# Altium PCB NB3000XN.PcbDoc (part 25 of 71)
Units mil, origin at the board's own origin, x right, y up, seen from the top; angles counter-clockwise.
Board outline 9527.56 x 6929.77 mil, 6 copper layers (Top Layer, GND+SHIELD, MidLayer1, MidLayer2, P2 - 3V3+5V0, Bottom Layer), stack 62.375 mil thick; 832 components, 1027 nets, 4655 pads, 4981 vias.
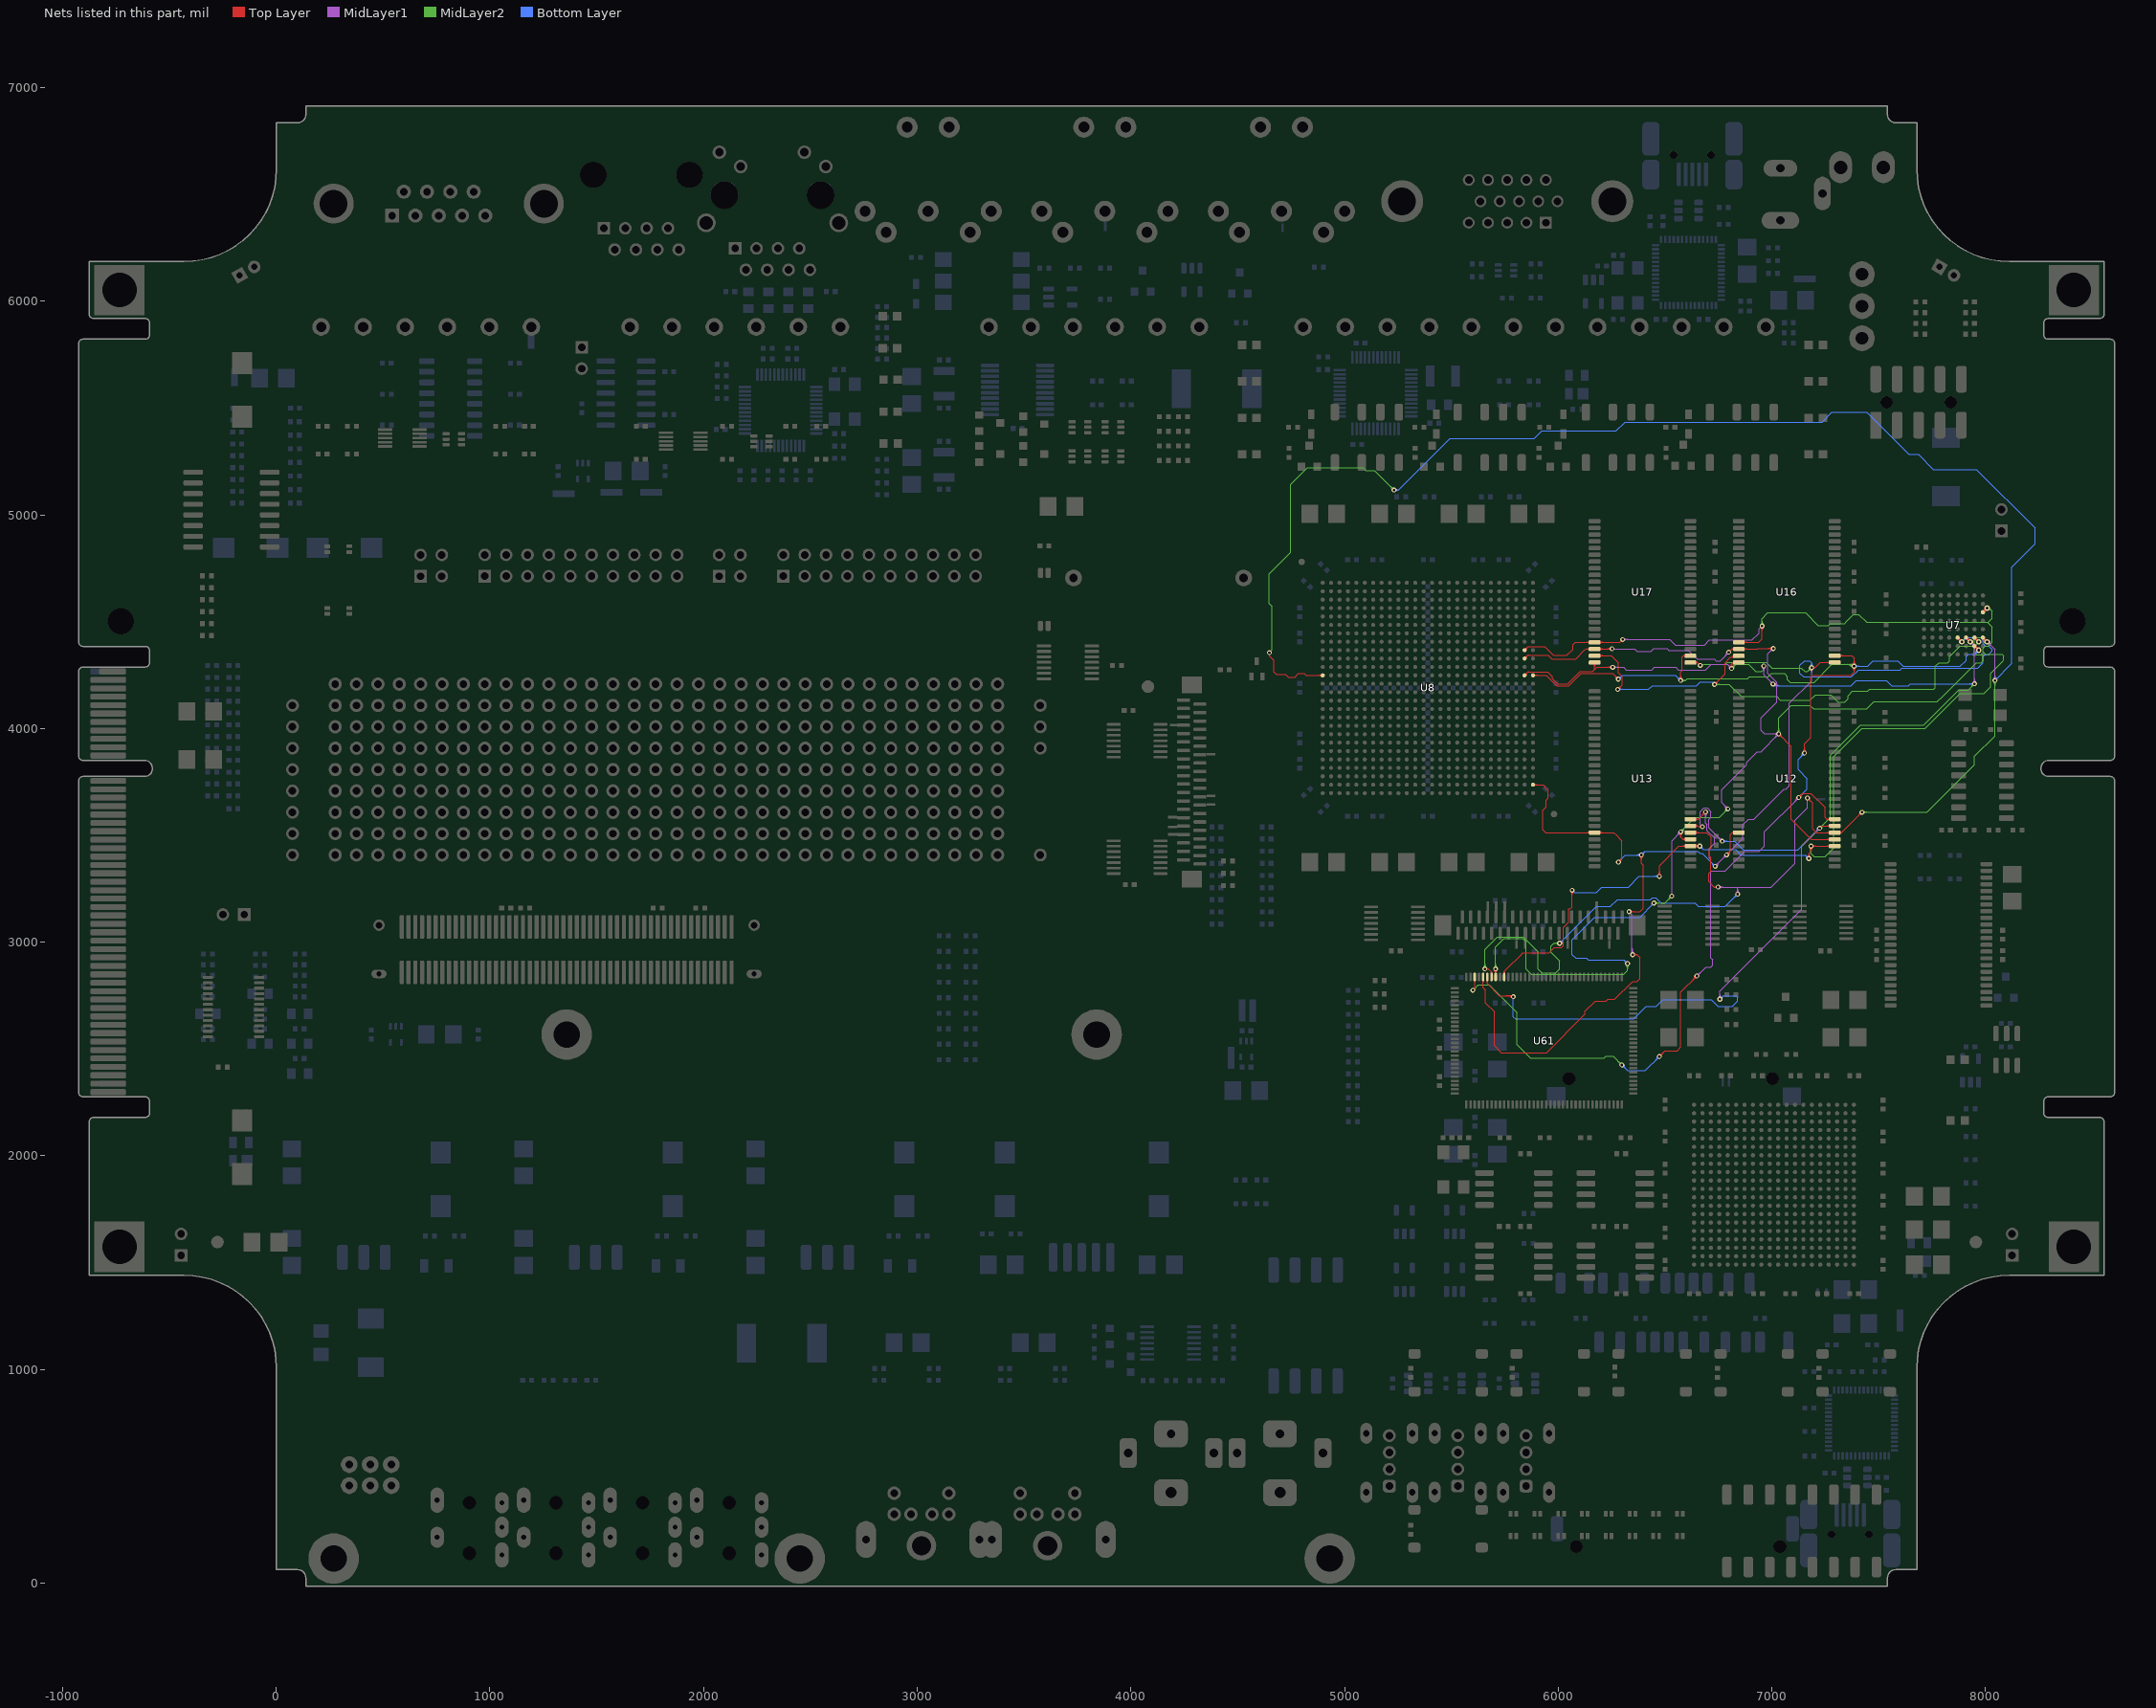
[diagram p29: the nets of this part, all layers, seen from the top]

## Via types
v1: diameter 23, hole 11.81, Top Layer to Bottom Layer, 3672 vias
v2: diameter 26, hole 11.81, Top Layer to Bottom Layer, 461 vias
v3: diameter 19, hole 11.81, Top Layer to Bottom Layer, tented both sides, 396 vias
v4: diameter 23.62, hole 11.81, Top Layer to Bottom Layer, 288 vias
v5: diameter 20, hole 11.81, Top Layer to Bottom Layer, 91 vias
v6: diameter 23, hole 11.81, Top Layer to Bottom Layer, tented both sides, 50 vias
v7: diameter 31, hole 11.81, Top Layer to Bottom Layer, 15 vias
v8: diameter 27.56, hole 11.81, Top Layer to Bottom Layer, tented both sides, 4 vias
v9: diameter 29, hole 11.81, Top Layer to Bottom Layer, 3 vias
v10: diameter 21, hole 11.81, Top Layer to Bottom Layer, 1 vias

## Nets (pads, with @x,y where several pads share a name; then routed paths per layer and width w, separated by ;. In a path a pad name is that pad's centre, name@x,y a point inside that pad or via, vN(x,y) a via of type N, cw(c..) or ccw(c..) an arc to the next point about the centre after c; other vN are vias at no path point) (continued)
DB_MEM.BUS_A8: U7.A3 U8.J25 U12.31 U13.31 U16.19 U17.19 U61.93 | length 7716.6
  Top Layer w4: U61.93@5744.34,2853.36 ccw(c5737.51,2860.19) 5747.17,2860.19 ccw(c5756.82,2860.19) U61.93@5749.99,2853.36 ; U61.93@5747.17,2837.34 5747.17,2862.68 5760.37,2875.89 5824.48,2940 5834.48,2950 5956.82,2950 5981.86,2975.04 6015.86,2975.04 6024.19,2983.37 6024.19,3070.04 6048.52,3094.37 6048.52,3154.04 6050.19,3155.71 6056.86,3155.71 6065.19,3164.04 v1(6065.19,3243.37) ; U8.J25@5842.76,4374.51 ccw(c5842.76,4392.23) 5855.29,4379.7 ; U8.J25@5850.1,4367.17 cw(c5867.83,4367.17) 5855.29,4379.7 ; v1@6058.47,3236.66 cw(c6042.26,3220.44) 6065.19,3220.44 cw(c6088.13,3220.44) v1@6071.91,3236.66 ; v1@6061.3,3239.49 cw(c6051.91,3230.1) 6065.19,3230.1 cw(c6078.47,3230.1) v1@6069.08,3239.49 ; U17.19@6147.37,4398.12 ccw(c6133.72,4384.47) 6133.72,4403.78 ccw(c6133.72,4423.09) U17.19@6147.37,4409.44 ; U17.19@6193.81,4398.12 cw(c6207.46,4384.47) 6207.46,4403.78 cw(c6207.46,4423.09) U17.19@6193.81,4409.44 ; v1(6301.86,4416.71) 6288.93,4403.78 U17.19@6170.59,4403.78 6080.86,4403.78 6068.86,4391.78 6068.86,4370.37 6041.19,4342.71 5976.52,4342.71 5936.56,4382.67 5924.74,4382.67 5920,4382.67 5910,4382.67 5862.47,4382.67 ccw(c5862.47,4372.52) 5855.29,4379.7 ; v1@6466.81,3315.09 ccw(c6450.59,3331.31) 6473.52,3331.31 ccw(c6496.46,3331.31) v1@6480.24,3315.09 ; v1@6469.64,3312.26 ccw(c6460.25,3321.65) 6473.52,3321.65 ccw(c6486.8,3321.65) v1@6477.41,3312.26 ; v1(6473.52,3308.37) 6473.52,3358.37 6565.19,3450.04 U13.31@6619.41,3450.04 ; U13.31@6596.19,3444.38 ccw(c6582.53,3430.72) 6582.53,3450.04 ccw(c6582.54,3469.35) U13.31@6596.19,3455.7 ; U13.31@6642.63,3444.38 cw(c6656.29,3430.72) 6656.29,3450.04 cw(c6656.28,3469.35) U13.31@6642.63,3455.7 ; v1@6656.14,3443.32 ccw(c6639.92,3427.11) 6639.92,3450.04 ccw(c6639.92,3472.98) v1@6656.14,3456.76 ; v1@6658.97,3446.15 ccw(c6649.58,3436.76) 6649.58,3450.04 ccw(c6649.58,3463.32) v1@6658.97,3453.93 ; v1(6662.86,3450.04) U13.31@6623.52,3450.04 ; U16.19@6845.59,4403.78 6938.78,4403.78 6954.52,4419.52 v1(6954.52,4480.04) ; U16.19@6868.81,4398.12 cw(c6882.46,4384.47) 6882.46,4403.78 cw(c6882.46,4423.09) U16.19@6868.81,4409.44 ; v1@6947.81,4473.32 cw(c6931.59,4457.11) 6954.52,4457.11 cw(c6977.46,4457.11) v1@6961.24,4473.32 ; v1@6950.64,4476.15 cw(c6941.25,4466.76) 6954.52,4466.76 cw(c6967.8,4466.76) v1@6958.41,4476.15 ; v1@7166.81,3398.43 ccw(c7150.59,3414.64) 7173.52,3414.64 ccw(c7196.46,3414.64) v1@7180.24,3398.43 ; v1@7169.64,3395.6 ccw(c7160.25,3404.99) 7173.52,3404.99 ccw(c7186.8,3404.99) v1@7177.41,3395.6 ; v1(7173.52,3391.71) 7173.52,3415 7183.52,3425 v1(7183.52,3450.04) U12.31@7276.86,3450.04 ; v1@7176.81,3443.32 cw(c7160.59,3427.11) 7183.52,3427.11 cw(c7206.46,3427.11) 7190.24,3443.32 cw(c7206.46,3427.11) 7206.46,3450.04 cw(c7206.46,3472.98) v1@7190.24,3456.76 ; v1@7179.64,3446.15 cw(c7170.25,3436.76) 7183.52,3436.76 cw(c7196.8,3436.76) 7187.41,3446.15 cw(c7196.8,3436.76) 7196.8,3450.04 cw(c7196.8,3463.32) v1@7187.41,3453.93 ; U12.31@7271.19,3444.38 ccw(c7257.53,3430.72) 7257.53,3450.04 ccw(c7257.54,3469.35) U12.31@7271.19,3455.7 ; U13.31@6619.41,3450.04 U13.31@6623.52,3450.04 ; U13.31@6619.41,3450.04 U13.31@6623.52,3450.04
  Top Layer w8: U7.A3@7987.8,4544.06 v2(8007.48,4563.74) ; U7.A3@7987.8,4550.06 ccw(c7987.8,4564.54) 7998.04,4554.3 ccw(c8008.28,4544.06) U7.A3@7993.8,4544.06 ; v2@7998.48,4563.74 cw(c7976.75,4563.74) 7992.12,4548.38 cw(c8007.48,4533.01) v2@8007.48,4554.74
  MidLayer1 w4: v1(6301.86,4416.71) 6522.51,4416.71 6548.01,4391.21 6684.75,4391.21 6707.75,4414.21 6907.5,4414.21 6940,4446.71 6940,4465.52 v1(6954.52,4480.04) ; v1@6305.75,4412.82 cw(c6315.14,4403.43) 6315.14,4416.71 cw(c6315.14,4429.99) v1@6305.75,4420.6 ; v1@6308.57,4409.99 cw(c6324.79,4393.77) 6324.79,4416.71 cw(c6324.79,4439.64) v1@6308.57,4423.43
  MidLayer2 w4: v1@6947.81,4486.76 ccw(c6931.59,4502.98) 6954.52,4502.98 ccw(c6977.46,4502.98) v1@6961.24,4486.76 ; v1@6950.64,4483.93 ccw(c6941.25,4493.32) 6954.52,4493.32 ccw(c6967.8,4493.32) v1@6958.41,4483.93 ; v1(6954.52,4480.04) 6954.52,4514.37 6981.86,4541.71 7156.86,4541.71 7215.52,4483.04 7265.88,4483.04 7274.88,4492.04 7340.52,4492.04 7348.52,4500.04 7381.86,4533.37 7406.86,4533.37 7443.19,4497.04 8012.19,4497.04 ; v1@7176.81,3443.32 cw(c7164.61,3431.13) 7181.86,3431.13 ; 7181.86,3423.08 cw(c7210.48,3423.08) v1@7190.24,3443.32 ; 7181.86,3432.74 cw(c7200.83,3432.74) v1@7187.41,3446.15 ; v1@7181.86,3448.37 7181.86,3416.71 7198.52,3400.04 7248.52,3400.04 7289.52,3441.04 7289.52,3868.41 7421.82,4000.71 7717.02,4000.71 7880.73,4164.42 7992.94,4164.42 8023.52,4195 8023.52,4258.37 8081.44,4316.29 ; v2@8007.28,4564.72 cw(c8010.41,4549.45) 8021.43,4560.47 ; v2(8007.48,4563.74) 8006.86,4563.74 8006.86,4566.71 8015.19,4566.71 8031.86,4550.04 8031.86,4516.71 8012.19,4497.04 ; v2@8008.08,4560.8 cw(c8012.19,4540.73) 8026.68,4555.22 ; v2@8008.88,4556.88 cw(c8013.98,4532) 8031.94,4549.96 ; 8081.44,4316.44 8085,4320 8085,4340 8077.29,4347.71 7999.19,4347.71 7988.19,4358.71 7988.19,4375.71 7998.52,4386.04 8014.19,4386.04 8031.86,4403.71 8031.86,4475.04 8011.02,4495.87 8012.19,4497.04
  Bottom Layer w4: v1(6065.19,3243.37) 6075.19,3233.37 6178.88,3233.37 6203.88,3258.37 6310,3258.37 6328.88,3258.37 6378.88,3308.37 v1(6473.52,3308.37) ; v1@6466.81,3301.66 ccw(c6450.59,3285.44) 6450.59,3308.37 ccw(c6450.59,3331.31) v1@6466.81,3315.09 ; v1@6469.64,3304.49 ccw(c6460.25,3295.1) 6460.25,3308.37 ccw(c6460.25,3321.65) v1@6469.64,3312.26 ; v1@6662.86,3440.54 cw(c6662.86,3417.61) 6679.08,3433.82 cw(c6695.29,3450.04) v1@6672.36,3450.04 ; v1@6662.86,3444.54 cw(c6662.86,3431.26) 6672.25,3440.65 cw(c6681.64,3450.04) v1@6668.36,3450.04 ; v1(6662.86,3450.04) 6679.52,3433.37 6831.25,3433.37 6856.25,3408.37 7156.86,3408.37 v1(7173.52,3391.71) ; v1@7164.02,3391.71 ccw(c7141.09,3391.71) 7157.31,3407.93 ccw(c7173.52,3424.14) v1@7173.52,3401.21 ; v1@7168.02,3391.71 ccw(c7154.75,3391.71) 7164.14,3401.1 ccw(c7173.52,3410.49) v1@7173.52,3397.21
DB_MEM.BUS_A9: U7.B6 U8.K25 U12.32 U13.32 U16.20 U17.20 U61.95 | length 8228
  Top Layer w4: v1@5700.14,2868.32 cw(c5681.66,2849.84) U61.95@5707.8,2849.84 ; v1@5702.97,2871.15 cw(c5691.31,2859.5) 5707.79,2859.5 ; U61.95@5704.97,2853.36 ccw(c5698.14,2860.19) 5707.8,2860.19 ccw(c5717.45,2860.19) U61.95@5710.62,2853.36 ; v1(5706.86,2875.04) 5707.79,2874.1 U61.95@5707.79,2837.34 ; U61.95@5707.8,2854.37 cw(c5727.53,2854.37) v1@5713.57,2868.32 ; 6002,4325 5971.6,4325 5971.56,4325.04 ; U17.20@6147.37,4366.63 ccw(c6133.72,4352.97) 6133.72,4372.28 ccw(c6133.72,4391.6) U17.20@6147.37,4377.94 ; U17.20@6193.81,4366.63 cw(c6207.46,4352.97) 6207.46,4372.28 cw(c6207.46,4391.6) U17.20@6193.81,4377.94 ; v1@6245.81,4366.66 ccw(c6229.59,4350.44) 6229.59,4373.37 ccw(c6229.59,4396.31) v1@6245.81,4380.09 ; v1@6248.64,4369.49 ccw(c6239.25,4360.1) 6239.25,4373.37 ccw(c6239.25,4386.65) v1@6248.64,4377.26 ; v1(6252.52,4373.37) 6222.52,4373.37 6221.43,4372.28 U17.20@6170.59,4372.28 6129.1,4372.28 ; v1@6566.81,3509.99 cw(c6550.59,3493.77) 6573.52,3493.77 cw(c6596.46,3493.77) v1@6580.24,3509.99 ; v1@6569.64,3512.82 cw(c6560.25,3503.43) 6573.52,3503.43 cw(c6586.8,3503.43) v1@6577.41,3512.82 ; v1(6573.52,3516.71) 6573.52,3491.71 6583.7,3481.53 ; U13.32@6595.95,3476.14 ccw(c6583.7,3464.94) 6583.7,3481.53 ; U13.32@6595.95,3486.93 cw(c6583.7,3498.13) 6583.7,3481.53 ; U13.32@6619.41,3481.54 6583.7,3481.53 ; v1(6798.52,4357.37) 6798.52,4358.04 6812.77,4372.28 ; U16.20@6821.45,4367.73 ccw(c6812.77,4361.72) 6812.77,4372.28 ; U16.20@6821.45,4376.84 cw(c6812.77,4382.85) 6812.77,4372.28 ; U16.20@6868.81,4366.63 cw(c6882.46,4352.97) 6882.46,4372.28 cw(c6882.46,4391.6) U16.20@6868.81,4377.94 ; v1@7000.14,4368.32 ccw(c6983.92,4352.11) 6983.92,4375.04 ccw(c6983.92,4397.98) v1@7000.14,4381.76 ; v1@7002.97,4371.15 ccw(c6993.58,4361.76) 6993.58,4375.04 ccw(c6993.58,4388.32) v1@7002.97,4378.93 ; v1(7006.86,4375.04) 6935.52,4375.04 6932.77,4372.28 U16.20@6845.59,4372.28 6812.77,4372.28 ; v1@7031.86,3965.54 cw(c7031.86,3942.61) 7048.07,3958.82 cw(c7064.29,3975.04) v1@7041.36,3975.04 ; v1@7031.86,3969.54 cw(c7031.86,3956.26) 7041.25,3965.65 cw(c7050.64,3975.04) v1@7037.36,3975.04 ; v1(7031.86,3975.04) 7090.19,3916.71 7090.19,3575.04 7183.7,3481.53 U12.32@7294.41,3481.54 ; U12.32@7271.19,3475.88 ccw(c7257.54,3462.22) 7257.54,3481.53 ccw(c7257.54,3500.85) U12.32@7271.19,3487.19 ; 5855.29,4340.33 cw(c5862.47,4333.15) 5862.47,4343.3 ; 5855.29,4340.33 cw(c5862.47,4333.15) 5862.47,4343.3 ; 5855.29,4340.33 cw(c5842.76,4352.86) 5842.76,4335.14 ccw(c5842.76,4352.86) 5855.29,4340.33 ; 5855.29,4340.33 ccw(c5867.83,4327.8) 5850.1,4327.8 cw(c5867.83,4327.8) 5855.29,4340.33 ; 5862.47,4343.3 5910,4343.3 5920,4343.3 ; 5920,4343.3 5924.74,4343.3 5925.06,4343.3 ; 5920,4343.3 5925.06,4343.3 ; 5925.06,4343.3 5928.74,4343.3 ; 5925.06,4343.3 5928.74,4343.31 ; 5928.74,4343.3 5943,4343.3 5949.72,4343.3 5953.3,4343.3 5971.56,4325.04 ; 5971.56,4325.04 6081.86,4325.04 6126.01,4369.19 ; 6126.01,4369.19 6129.1,4372.28 ; 6126.01,4369.19 6129.1,4372.28
  Top Layer w8: U7.B6@7948.43,4419.94 cw(c7948.43,4405.46) 7958.67,4415.7 cw(c7968.91,4425.94) U7.B6@7954.43,4425.94 ; U7.B6@7948.43,4425.94 v2(7968.11,4406.26) ; v2@7959.11,4406.26 ccw(c7937.38,4406.26) 7952.75,4421.62 ccw(c7968.11,4436.99) v2@7968.11,4415.26
  MidLayer1 w4: v1(6252.52,4373.37) 6358.21,4373.37 6369.21,4362.37 6435.17,4362.37 6447.84,4375.04 6509.84,4375.04 6518.17,4366.71 6609.61,4366.71 6651.27,4325.04 6731.27,4325.04 6738.94,4317.37 6758.52,4317.37 v1(6798.52,4357.37) ; v1(6531.86,3215.71) 6531.86,3475.04 v1(6573.52,3516.71) ; v1@6564.02,3516.71 cw(c6541.09,3516.71) 6557.31,3500.49 cw(c6573.52,3484.27) v1@6573.52,3507.21 ; v1@6568.02,3516.71 cw(c6554.75,3516.71) 6564.14,3507.32 cw(c6573.52,3497.93) v1@6573.52,3511.21 ; v1@6785.02,3624.04 ccw(c6762.09,3624.04) 6778.31,3640.26 ccw(c6794.52,3656.48) v1@6794.52,3633.54 ; v1@6789.02,3624.04 ccw(c6775.75,3624.04) 6785.14,3633.43 ccw(c6794.52,3642.82) v1@6794.52,3629.54 ; v1@6789.02,4357.37 cw(c6766.09,4357.37) 6782.31,4341.16 cw(c6798.52,4324.94) v1@6798.52,4347.87 ; v1@6793.02,4357.37 cw(c6779.75,4357.37) 6789.14,4347.99 cw(c6798.52,4338.6) v1@6798.52,4351.87 ; v1(6794.52,3624.04) 6765.19,3653.37 6765.19,3714.71 6881.86,3831.37 6881.86,3841.71 6931.86,3891.71 6948.52,3891.71 v1(7031.86,3975.04) 6965.19,3975.04 6948.52,3991.71 6948.52,4049.37 7023.52,4124.37 7023.52,4216.37 6981.86,4258.04 6981.86,4350.04 v1(7006.86,4375.04) ; v1@6997.36,4375.04 cw(c6974.42,4375.04) 6990.64,4358.82 cw(c7006.86,4342.61) v1@7006.86,4365.54 ; v1@7001.36,4375.04 cw(c6988.08,4375.04) 6997.47,4365.65 cw(c7006.86,4356.26) v1@7006.86,4369.54 ; v1@7022.36,3975.04 cw(c6999.42,3975.04) 7015.64,3958.82 cw(c7031.86,3942.61) v1@7031.86,3965.54 ; v1@7025.14,3968.32 ccw(c7008.92,3952.11) 7008.92,3975.04 ccw(c7008.92,3997.98) v1@7025.14,3981.76 ; v1@7026.36,3975.04 cw(c7013.08,3975.04) 7022.47,3965.65 cw(c7031.86,3956.26) v1@7031.86,3969.54 ; v1@7027.97,3971.15 ccw(c7018.58,3961.76) 7018.58,3975.04 ccw(c7018.58,3988.32) v1@7027.97,3978.93
  MidLayer2 w4: v1@5700.14,2881.76 ccw(c5683.92,2897.98) 5706.86,2897.98 ccw(c5729.79,2897.98) v1@5713.57,2881.76 ; v1@5702.97,2878.93 ccw(c5693.58,2888.32) 5706.86,2888.32 ccw(c5720.14,2888.32) v1@5710.75,2878.93 ; v1(5706.86,2875.04) 5706.86,2977.71 5745.86,3016.71 5834.23,3016.71 5850,3000.94 5850,2873.56 5874.19,2849.37 6306.56,2849.37 6324.52,2867.34 v1(6324.52,2900.04) ; v1@6317.81,2893.32 cw(c6301.59,2877.11) 6324.52,2877.11 cw(c6347.46,2877.11) v1@6331.24,2893.32 ; v1@6320.64,2896.15 cw(c6311.25,2886.76) 6324.52,2886.76 cw(c6337.8,2886.76) v1@6328.41,2896.15 ; v1(6448.52,3183.37) 6499.52,3183.37 v1(6531.86,3215.71) ; v1@6452.41,3179.49 cw(c6461.8,3170.1) 6461.8,3183.37 cw(c6461.8,3196.65) v1@6452.41,3187.26 ; v1@6455.24,3176.66 cw(c6471.46,3160.44) 6471.46,3183.37 cw(c6471.46,3206.31) v1@6455.24,3190.09 ; v1@6522.36,3215.71 cw(c6499.42,3215.71) 6515.64,3199.49 cw(c6531.86,3183.27) v1@6531.86,3206.21 ; v1@6526.36,3215.71 cw(c6513.08,3215.71) 6522.47,3206.32 cw(c6531.86,3196.93) v1@6531.86,3210.21 ; v1(6573.52,3516.71) 6640.19,3583.37 6753.86,3583.37 v1(6794.52,3624.04) ; v1@6573.52,3522.21 ccw(c6573.52,3535.49) 6582.91,3526.1 ccw(c6592.3,3516.71) v1@6579.02,3516.71 ; v1@6573.52,3526.21 ccw(c6573.52,3549.14) 6589.74,3532.93 ccw(c6605.96,3516.71) v1@6583.02,3516.71 ; v1@6785.02,3624.04 cw(c6762.09,3624.04) 6778.31,3607.82 cw(c6794.52,3591.61) v1@6794.52,3614.54 ; v1@6789.02,3624.04 cw(c6775.75,3624.04) 6785.13,3614.65 cw(c6794.52,3605.26) v1@6794.52,3618.54 ; v1@7025.14,3981.76 ccw(c7008.92,3997.98) 7031.86,3997.98 ccw(c7054.79,3997.98) v1@7038.57,3981.76 ; v1@7027.97,3978.93 ccw(c7018.58,3988.32) 7031.86,3988.32 ccw(c7045.14,3988.32) v1@7035.75,3978.93 ; v1(7031.86,3975.04) 7031.86,4050.04 7090.19,4108.37 7178.88,4108.37 7195.21,4092.04 7443.5,4092.04 7476.84,4125.37 7773.86,4125.37 7799.76,4151.28 7956.86,4308.37 7979.52,4308.37 7987.86,4316.71 7987.86,4345.04 7986.19,4346.71 7957.86,4346.71 7948.52,4356.04 7948.52,4386.67 v2(7968.11,4406.26)
  Bottom Layer w4: v1@6315.02,2900.04 ccw(c6292.09,2900.04) 6308.31,2916.26 ccw(c6324.52,2932.48) v1@6324.52,2909.54 ; v1@6319.02,2900.04 ccw(c6305.75,2900.04) 6315.14,2909.43 ccw(c6324.52,2918.82) v1@6324.52,2905.54 ; v1(6324.52,2900.04) 6306.86,2917.71 6165.19,2917.71 6164.19,2916.71 6140.19,2916.71 6131.86,2925.04 6081.86,2925.04 6065.19,2941.71 6065.19,3011.04 6170.86,3116.71 6381.86,3116.71 v1(6448.52,3183.37) ; v1@6439.02,3183.37 cw(c6416.09,3183.37) 6432.31,3167.16 cw(c6448.52,3150.94) v1@6448.52,3173.87 ; v1@6443.02,3183.37 cw(c6429.75,3183.37) 6439.14,3173.99 cw(c6448.52,3164.6) v1@6448.52,3177.87
DB_MEM.BUS_A10: U7.A6 U8.M1 U12.33 U13.33 U16.21 U17.21 U61.96 | length 14451.3
  Top Layer w4: v1(4648.52,4355.04) 4648.52,4339.71 4670.52,4317.71 4670.52,4264.37 4681.86,4253.04 4723.52,4253.04 4735.86,4240.71 4767.17,4240.71 4784.34,4257.87 4811.11,4257.87 4819.93,4249.05 4856.86,4249.05 ; 4855.26,4249.06 4860,4249.06 4870,4249.06 U8.M1@4897.87,4249.06 ; U8.M1@4892.57,4243.75 ccw(c4879.77,4230.95) 4879.77,4249.06 ccw(c4879.77,4267.16) U8.M1@4892.57,4254.36 ; U8.M1@4892.68,4243.86 ccw(c4880.15,4231.33) 4880.15,4249.06 ccw(c4880.15,4266.78) U8.M1@4892.68,4254.25 ; v1(5656.86,2875.04) 5673.52,2875.04 ; v1@5665.03,2870.2 cw(c5673.52,2865.17) 5673.52,2875.04 ; v1@5665.03,2879.88 ccw(c5673.52,2884.91) 5673.52,2875.04 ; U61.96@5685.28,2853.36 ccw(c5678.45,2860.19) 5688.11,2860.19 ccw(c5697.77,2860.19) U61.96@5690.94,2853.36 ; U61.96@5688.11,2837.34 5688.11,2860.45 5673.52,2875.04 ; U17.21@6170.59,4340.79 6249.44,4340.79 6281.86,4308.37 6281.86,4261.04 6299.86,4243.04 6299.86,4204.71 v1(6278.52,4183.37) ; U17.21@6193.81,4335.13 cw(c6207.46,4321.47) 6207.46,4340.79 cw(c6207.46,4360.1) U17.21@6193.81,4346.44 ; v1@6278.52,4188.87 ccw(c6278.52,4202.15) 6287.91,4192.76 ccw(c6297.3,4183.37) v1@6284.02,4183.37 ; v1@6278.52,4192.87 ccw(c6278.52,4215.81) 6294.74,4199.59 ccw(c6310.96,4183.37) v1@6288.02,4183.37 ; U13.33@6619.41,3513.03 6695.2,3513.03 6716.52,3491.71 6716.52,3443.04 6706.86,3433.37 6706.86,3403.69 6715.19,3395.35 6715.19,3331.35 6705,3321.16 6705,3283.37 6730,3258.37 ; U13.33@6642.63,3507.37 cw(c6656.28,3493.72) 6656.28,3513.03 cw(c6656.28,3532.35) U13.33@6642.63,3518.69 ; v1(6731.86,4206.71) 6781.86,4256.71 6781.86,4308.37 6806.86,4333.37 ; v1@6731.86,4212.21 ccw(c6731.86,4225.49) 6741.25,4216.1 ccw(c6750.64,4206.71) v1@6737.36,4206.71 ; v1@6731.86,4216.21 ccw(c6731.86,4239.14) 6748.07,4222.93 ccw(c6764.29,4206.71) v1@6741.36,4206.71 ; v1@6740.81,3252.83 ccw(c6730,3245.07) 6730,3258.37 ; v1@6740.81,3263.92 cw(c6730,3271.68) 6730,3258.37 ; v1(6748.52,3258.37) 6730,3258.37 ; 6812.35,4333.37 ccw(c6812.35,4345.85) U16.21@6824.23,4342.02 ; 6817.85,4333.37 ccw(c6817.85,4344.08) U16.21@6828.03,4340.79 ; U16.21@6820.42,4343.25 cw(c6806.86,4347.62) 6806.86,4333.37 ; U16.21@6845.59,4340.79 6848.52,4340.79 6848.52,4333.37 6845.59,4333.37 6806.86,4333.37 ; v1@7166.52,3665.54 cw(c7166.52,3642.61) 7182.74,3658.82 cw(c7198.96,3675.04) v1@7176.02,3675.04 ; v1@7166.52,3669.54 cw(c7166.52,3656.26) 7175.91,3665.65 cw(c7185.3,3675.04) v1@7172.02,3675.04 ; v1(7166.52,3675.04) 7190.19,3651.37 7190.19,3529.7 7206.86,3513.03 7326.51,3513.03 ; U12.33@7271.19,3507.37 ccw(c7257.54,3493.72) 7257.54,3513.03 ccw(c7257.54,3532.35) U12.33@7271.19,3518.69 ; U12.33@7318.72,3508.75 cw(c7326.51,3503.81) 7326.51,3513.03 ; U12.33@7318.73,3517.31 ccw(c7326.51,3522.25) 7326.51,3513.03 ; v1@7412.36,3608.37 cw(c7389.42,3608.37) 7405.64,3592.16 cw(c7421.86,3575.94) v1@7421.86,3598.87 ; v1@7416.36,3608.37 cw(c7403.08,3608.37) 7412.47,3598.99 cw(c7421.86,3589.6) v1@7421.86,3602.87 ; v1(7421.86,3608.37) 7326.51,3513.03
  Top Layer w8: U7.A6@7987.8,4419.94 cw(c7987.8,4405.46) 7998.04,4415.7 cw(c8008.28,4425.94) U7.A6@7993.8,4425.94 ; U7.A6@7987.8,4425.94 v2(8007.48,4406.26) ; v2@7998.48,4406.26 ccw(c7976.75,4406.26) 7992.12,4421.62 ccw(c8007.48,4436.99) v2@8007.48,4415.26
  MidLayer1 w4: v1(6748.52,3258.37) 6840.19,3258.37 ; v1@6752.41,3254.49 cw(c6761.8,3245.1) 6761.8,3258.37 cw(c6761.8,3271.65) v1@6752.41,3262.26 ; v1@6755.24,3251.66 cw(c6771.46,3235.44) 6771.46,3258.37 cw(c6771.46,3281.31) v1@6755.24,3265.09 ; v1@6833.47,3231.76 ccw(c6817.26,3247.98) 6840.19,3247.98 ccw(c6863.13,3247.98) v1@6846.91,3231.76 ; v1@6836.3,3228.93 ccw(c6826.91,3238.32) 6840.19,3238.32 ccw(c6853.47,3238.32) v1@6844.08,3228.93 ; v1(6840.19,3225.04) 6840.19,3258.37 ; v1(7166.52,3675.04) 7166.52,3629.36 7107.52,3570.36 7107.52,3370.35 6995.54,3258.37 6840.19,3258.37 ; v2@8007.48,4395.26 cw(c8007.48,4368.7) 8026.26,4387.48 cw(c8045.04,4406.26) v2@8018.48,4406.26 ; v2@8007.48,4399.26 cw(c8007.48,4382.36) 8019.43,4394.31 cw(c8031.38,4406.26) v2@8014.48,4406.26 ; v2(8007.48,4406.26) 8043.86,4369.88 v1(8043.86,4225.04) ; v1@8037.14,4231.76 ccw(c8020.92,4247.98) 8043.86,4247.98 ccw(c8066.79,4247.98) v1@8050.57,4231.76 ; v1@8039.97,4228.93 ccw(c8030.58,4238.32) 8043.86,4238.32 ccw(c8057.14,4238.32) v1@8047.75,4228.93
  MidLayer2 w4: v1(4648.52,4355.04) 4661.19,4367.71 4661.19,4572.04 4648.19,4585.04 4648.19,4724.71 4685.26,4761.78 4748.52,4825.04 4748.52,5143.69 4826.03,5221.19 5088,5221.19 5100.65,5208.54 5140.02,5208.54 v1(5231.86,5116.71) ; v1@5222.36,5116.71 ccw(c5199.42,5116.71) 5215.64,5132.93 ccw(c5231.86,5149.14) v1@5231.86,5126.21 ; v1@5226.36,5116.71 ccw(c5213.08,5116.71) 5222.47,5126.1 ccw(c5231.86,5135.49) v1@5231.86,5122.21 ; v1@5650.14,2881.76 ccw(c5633.92,2897.98) 5656.86,2897.98 ccw(c5679.79,2897.98) v1@5663.57,2881.76 ; v1@5652.97,2878.93 ccw(c5643.58,2888.32) 5656.86,2888.32 ccw(c5670.14,2888.32) v1@5660.75,2878.93 ; v1(5656.86,2875.04) 5656.86,2966.71 5715.19,3025.04 5837.21,3025.04 5906.86,2955.39 5906.86,2875.04 5924.52,2857.37 5989.19,2857.37 6006.86,2875.04 6006.86,2912.04 5966.86,2952.04 5966.86,2981.86 5980.04,2995.04 v1(6006.52,2995.04) ; v1@5999.81,2988.32 ccw(c5983.59,2972.11) 5983.59,2995.04 ccw(c5983.59,3017.98) v1@5999.81,3001.76 ; v1@6002.64,2991.15 ccw(c5993.25,2981.76) 5993.25,2995.04 ccw(c5993.25,3008.32) v1@6002.64,2998.93 ; v1(6731.86,4206.71) 6800.19,4206.71 6856.86,4150.04 7022.52,4150.04 7039.19,4133.37 7178.88,4133.37 7203.88,4158.37 7276.5,4158.37 7309.84,4125.04 7341.19,4125.04 7356.86,4140.71 7356.86,4153.37 7377.86,4174.37 7447.86,4174.37 7456.86,4183.37 7756.86,4183.37 7765.19,4191.71 7765.19,4291.71 7781.86,4308.37 7823.52,4308.37 7831.86,4316.71 7831.86,4336.71 7881.19,4386.04 7935.86,4386.04 7948.52,4398.71 7948.52,4414.04 7960.52,4426.04 7981.86,4426.04 7993.52,4414.37 7993.52,4406.25 v2(8007.48,4406.26) ; v1@6735.75,4202.82 cw(c6745.14,4193.43) 6745.14,4206.71 cw(c6745.14,4219.99) v1@6735.75,4210.6 ; v1@6738.57,4199.99 cw(c6754.79,4183.77) 6754.79,4206.71 cw(c6754.79,4229.64) v1@6738.57,4213.43 ; v1(7421.86,3608.37) 7725.9,3608.37 7948.52,3831 7948.52,3870.02 8043.86,3965.35 v1(8043.86,4225.04) ; v1@7425.75,3604.49 cw(c7435.14,3595.1) 7435.14,3608.37 cw(c7435.14,3621.65) v1@7425.75,3612.26 ; v1@7428.57,3601.66 cw(c7444.79,3585.44) 7444.79,3608.37 cw(c7444.79,3631.31) v1@7428.57,3615.09 ; v1@8037.14,4218.32 cw(c8020.92,4202.11) 8043.86,4202.11 cw(c8066.79,4202.11) v1@8050.57,4218.32 ; v1@8039.97,4221.15 cw(c8030.58,4211.76) 8043.86,4211.76 cw(c8057.14,4211.76) v1@8047.75,4221.15
  Bottom Layer w4: v1(5231.86,5116.71) 5251.71,5116.71 ; v1@5239.26,5110.75 cw(c5251.71,5100.72) 5251.71,5116.71 ; v1@5239.26,5122.67 ccw(c5251.71,5132.7) 5251.71,5116.71 ; v1(6006.52,2995.04) 6178.19,3166.71 6243.17,3166.71 6276.5,3200.04 6431.86,3200.04 6440.19,3208.37 6456.86,3208.37 6481.86,3183.37 6640.19,3183.37 6656.86,3166.71 6781.86,3166.71 v1(6840.19,3225.04) ; v1@6006.52,3000.54 ccw(c6006.52,3013.82) 6015.91,3004.43 ccw(c6025.3,2995.04) v1@6012.02,2995.04 ; v1@6006.52,3004.54 ccw(c6006.52,3027.48) 6022.74,3011.26 ccw(c6038.96,2995.04) v1@6016.02,2995.04 ; v1(6278.52,4183.37) 6423.37,4183.37 6440.04,4200.04 6647.19,4200.04 6665.19,4218.04 6720.52,4218.04 v1(6731.86,4206.71) ; v1@6282.41,4179.49 cw(c6291.8,4170.1) 6291.8,4183.37 cw(c6291.8,4196.65) v1@6282.41,4187.26 ; v1@6285.24,4176.66 cw(c6301.46,4160.44) 6301.46,4183.37 cw(c6301.46,4206.31) v1@6285.24,4190.09 ; v1@6830.69,3225.04 cw(c6807.76,3225.04) 6823.97,3208.82 cw(c6840.19,3192.61) v1@6840.19,3215.54 ; v1@6834.69,3225.04 cw(c6821.41,3225.04) 6830.8,3215.65 cw(c6840.19,3206.26) v1@6840.19,3219.54 ; v1(8043.86,4225.04) 8123.86,4305.04 8123.86,4756.48 8231.86,4864.48 8231.86,4938.12 7956.86,5213.12 7755.57,5213.12 7685.31,5283.37 7641.63,5283.37 7445,5480 7280,5480 7235,5435 6313.25,5435 6271.63,5393.37 5922.82,5393.37 5887.82,5358.37 5493.37,5358.37 5251.71,5116.71 ; v1@8043.86,4230.54 ccw(c8043.86,4243.82) 8053.25,4234.43 ccw(c8062.64,4225.04) v1@8049.36,4225.04 ; v1@8043.86,4234.54 ccw(c8043.86,4257.48) 8060.07,4241.26 ccw(c8076.29,4225.04) v1@8053.36,4225.04
DB_MEM.BUS_A11: U7.C6 U8.M25 U12.34 U13.34 U16.22 U17.22 U61.97 | length 8754.7
  Top Layer w4: U61.97@5665.6,2821.32 cw(c5658.77,2814.49) 5668.43,2814.49 cw(c5678.08,2814.49) U61.97@5671.25,2821.32 ; U61.97@5668.42,2837.34 5668.42,2806.57 5724.96,2750.04 5785.15,2750.04 v1(5790.19,2745) ; 5755.09,2750.04 cw(c5755.09,2709.9) v1@5783.47,2738.28 ; 5764.74,2750.04 cw(c5764.74,2719.55) v1@5786.3,2741.11 ; 5774.4,2750.04 cw(c5774.4,2729.21) v1@5789.13,2743.94 ; 5779.42,2750.04 ccw(c5779.42,2755.77) v1@5783.47,2751.72 ; U8.M25@5842.76,4256.4 ccw(c5842.76,4274.12) 5855.29,4261.59 ; U8.M25@5850.1,4249.06 cw(c5867.83,4249.06) 5855.29,4261.59 ; U17.22@6164.93,4303.64 cw(c6151.28,4289.98) 6170.59,4289.98 cw(c6189.9,4289.98) U17.22@6176.25,4303.64 ; U17.22@6170.59,4309.29 6170.59,4275.71 ; v1@6248.47,4279.99 ccw(c6232.26,4263.77) 6232.26,4286.71 ccw(c6232.26,4309.64) v1@6248.47,4293.43 ; v1@6251.3,4282.82 ccw(c6241.91,4273.43) 6241.91,4286.71 ccw(c6241.91,4299.99) v1@6251.3,4290.6 ; v1(6255.19,4286.71) 6181.59,4286.71 6170.59,4275.71 ; U13.34@6619.41,3544.53 6653.71,3544.53 ; U13.34@6643.19,3539.5 cw(c6653.7,3531.02) 6653.7,3544.53 ; U13.34@6643.19,3549.55 ccw(c6653.7,3558.03) 6653.7,3544.53 ; v1@6666.85,3535.6 ccw(c6657.52,3529.65) 6657.52,3540.71 ; v1@6666.85,3545.82 cw(c6657.52,3551.77) 6657.52,3540.71 ; v1(6674.86,3540.71) 6657.52,3540.71 ; v1@6805.55,4288.76 ccw(c6795.4,4301.29) 6811.52,4301.29 ; v1@6808.06,4285.65 ccw(c6802.19,4292.9) 6811.52,4292.9 ccw(c6820.86,4292.9) v1@6814.99,4285.65 ; v1(6811.52,4281.37) 6811.52,4301.29 ; 6811.98,4301.75 cw(c6822.52,4291.21) U16.22@6826.86,4305.47 ; 6816.69,4306.46 cw(c6824.72,4298.43) U16.22@6828.03,4309.29 ; v1@6817.5,4288.76 cw(c6827.65,4301.29) 6811.52,4301.29 ; U16.22@6845.59,4309.29 6819.52,4309.29 6811.52,4301.29 ; v1(7223.52,3533.37) 7234.68,3544.53 U12.34@7294.41,3544.53 ; U12.34@7271.19,3538.87 ccw(c7257.54,3525.22) 7257.54,3544.53 ccw(c7257.54,3563.84) U12.34@7271.19,3550.18 ; 5855.29,4261.59 cw(c5862.47,4254.41) 5862.47,4264.56 5910,4264.56 5920,4264.56 5924.74,4264.56 5951.67,4264.56 5973.52,4242.71 5973.52,4233.37 5998.52,4208.37 6045.54,4208.37 6103.88,4266.71 6161.59,4266.71 6170.59,4275.71 ; 6653.71,3544.53 6657.52,3540.71
  Top Layer w8: U7.C6@7909.06,4419.94 cw(c7909.06,4405.46) 7919.3,4415.7 cw(c7929.54,4425.94) U7.C6@7915.06,4425.94 ; U7.C6@7909.06,4425.94 v2(7928.74,4406.26) ; v2@7919.74,4406.26 ccw(c7898.01,4406.26) 7913.38,4421.62 ccw(c7928.74,4436.99) v2@7928.74,4415.26
  MidLayer1 w4: v1@6258.52,4283.37 v1(6255.19,4286.71) 6306.67,4286.71 6318.67,4274.71 6438.39,4274.71 6450.22,4286.54 6551.32,4286.54 6562.82,4275.04 6690.19,4275.04 6716.52,4301.37 6791.52,4301.37 v1(6811.52,4281.37) ; v1@6259.08,4282.82 cw(c6268.47,4273.43) 6268.47,4286.71 cw(c6268.47,4299.99) v1@6259.08,4290.6 ; v1@6261.91,4279.99 cw(c6278.13,4263.77) 6278.13,4286.71 cw(c6278.13,4309.64) v1@6261.91,4293.43 ; v1(6674.86,3540.71) 6665.19,3550.37 6665.19,3611.37 6681.86,3628.04 6698.52,3628.04 6715.19,3611.37 6715.19,3585.04 6705.19,3575.04 6705.19,3535.37 v1(6767.52,3473.04) ; v1@6750.14,2740.09 ccw(c6733.92,2756.31) 6756.86,2756.31 ccw(c6779.79,2756.31) v1@6763.57,2740.09 ; v1@6752.97,2737.26 ccw(c6743.58,2746.65) 6756.86,2746.65 ccw(c6770.14,2746.65) v1@6760.75,2737.26 ; v1(6756.86,2733.37) 6756.86,2772.06 7139.86,3155.06 7139.86,3449.71 7159.95,3469.8 ; v1@6758.02,3473.04 ccw(c6735.09,3473.04) 6751.31,3489.26 ccw(c6767.52,3505.48) v1@6767.52,3482.54 ; v1@6762.02,3473.04 ccw(c6748.75,3473.04) 6758.14,3482.43 ccw(c6767.52,3491.82) v1@6767.52,3478.54 ; v1@6802.02,4281.37 ccw(c6779.09,4281.37) 6795.31,4297.59 ccw(c6811.52,4313.81) v1@6811.52,4290.87 ; v1@6806.02,4281.37 ccw(c6792.75,4281.37) 6802.14,4290.76 ccw(c6811.52,4300.15) v1@6811.52,4286.87 ; v1@6955.47,4286.32 cw(c6939.26,4270.11) 6962.19,4270.11 cw(c6985.13,4270.11) v1@6968.91,4286.32 ; v1@6958.3,4289.15 cw(c6948.91,4279.76) 6962.19,4279.76 cw(c6975.47,4279.76) v1@6966.08,4289.15 ; v1(6962.19,4293.04) 6962.19,4251.37 v1(7005.19,4208.37) ; v1@6995.69,4208.37 ccw(c6972.76,4208.37) 6988.97,4224.59 ccw(c7005.19,4240.81) v1@7005.19,4217.87 ; v1@6999.69,4208.37 ccw(c6986.41,4208.37) 6995.8,4217.76 ccw(c7005.19,4227.15) v1@7005.19,4213.87 ; 7148.52,3458.37 v1(7223.52,3533.37) ; v1@7214.02,3533.37 cw(c7191.09,3533.37) 7207.31,3517.16 cw(c7223.52,3500.94) v1@7223.52,3523.87 ; v1@7218.02,3533.37 cw(c7204.75,3533.37) 7214.14,3523.99 cw(c7223.52,3514.6) v1@7223.52,3527.87 ; v2@7928.74,4395.26 cw(c7928.74,4368.7) 7947.52,4387.48 cw(c7966.3,4406.26) v2@7939.74,4406.26 ; v2@7928.74,4399.26 cw(c7928.74,4382.36) 7940.69,4394.31 cw(c7952.64,4406.26) v2@7935.74,4406.26 ; v2(7928.74,4406.26) 7948.52,4386.48 v1(7948.52,4209.71) ; v1@7941.81,4216.43 ccw(c7925.59,4232.64) 7948.52,4232.64 ccw(c7971.46,4232.64) v1@7955.24,4216.43 ; v1@7944.64,4213.6 ccw(c7935.25,4222.99) 7948.52,4222.99 ccw(c7961.8,4222.99) v1@7952.41,4213.6
  MidLayer2 w4: v1(6811.52,4281.37) 6831.19,4301.04 6890.19,4301.04 6924.52,4266.71 6952.52,4266.71 6962.19,4276.37 ; v1@6811.52,4286.87 ccw(c6811.52,4300.15) 6820.91,4290.76 ccw(c6830.3,4281.37) v1@6817.02,4281.37 ; v1@6811.52,4290.87 ccw(c6811.52,4313.81) 6827.74,4297.59 ccw(c6843.96,4281.37) v1@6821.02,4281.37 ; v1@6957.35,4284.87 cw(c6952.32,4276.38) 6962.19,4276.38 ; v1(6962.19,4293.04) 6962.19,4276.37 ; v1@6967.03,4284.87 ccw(c6972.06,4276.38) 6962.19,4276.38 ; v1(7223.52,3533.37) 7273.52,3583.37 7273.52,3875.04 7415.19,4016.71 7709.84,4016.71 7873.55,4180.42 7919.23,4180.42 v1(7948.52,4209.71) ; v1@7223.52,3538.87 ccw(c7223.52,3552.15) 7232.91,3542.76 ccw(c7242.3,3533.37) v1@7229.02,3533.37 ; v1@7223.52,3542.87 ccw(c7223.52,3565.81) 7239.74,3549.59 ccw(c7255.96,3533.37) v1@7233.02,3533.37 ; v1@7939.02,4209.71 cw(c7916.09,4209.71) 7932.31,4193.49 cw(c7948.52,4177.27) v1@7948.52,4200.21 ; v1@7943.02,4209.71 cw(c7929.75,4209.71) 7939.14,4200.32 cw(c7948.52,4190.93) v1@7948.52,4204.21
  Bottom Layer w4: v1(5790.19,2745) 5790.19,2651.33 5799.82,2641.71 6354.17,2641.71 6412.5,2700.04 6460,2700.04 6491,2731.04 6716.02,2731.04 6747.02,2700.04 6815.19,2700.04 6840.19,2725.04 6840.19,2741.71 6831.86,2750.04 6773.52,2750.04 v1(6756.86,2733.37) ; v1@6756.86,2738.87 ccw(c6756.86,2752.15) 6766.25,2742.76 ccw(c6775.64,2733.37) v1@6762.36,2733.37 ; v1@6756.86,2742.87 ccw(c6756.86,2765.81) 6773.08,2749.59 ccw(c6789.29,2733.37) v1@6766.36,2733.37 ; v1(6767.52,3473.04) 6825.52,3473.04 6866.19,3432.37 7122.52,3432.37 v1(7223.52,3533.37) ; v1@6771.41,3469.15 cw(c6780.8,3459.76) 6780.8,3473.04 cw(c6780.8,3486.32) v1@6771.41,3476.93 ; v1@6774.24,3466.32 cw(c6790.46,3450.11) 6790.46,3473.04 cw(c6790.46,3495.98) v1@6774.24,3479.76 ; v1@7003.42,4206.61 ccw(c7019.27,4222.46) 7019.27,4200.04 ; v1(7005.19,4208.37) 7013.52,4200.04 7370.52,4200.04 7394.86,4224.37 7440,4224.37 7451.19,4224.37 7535.67,4224.37 7560,4200.04 7639.19,4200.04 7648.86,4209.71 v1(7948.52,4209.71) ; v1@7006.25,4209.44 ccw(c7028.93,4232.12) 7028.93,4200.04 ; v1@7009.08,4212.26 ccw(c7038.59,4241.77) 7038.59,4200.04 ; v1@7011.91,4215.09 ccw(c7048.25,4251.43) 7048.25,4200.04 ; v1@7214.02,3533.37 cw(c7191.09,3533.37) 7207.31,3517.16 cw(c7223.52,3500.94) v1@7223.52,3523.87 ; v1@7218.02,3533.37 cw(c7204.75,3533.37) 7214.14,3523.99 cw(c7223.52,3514.6) v1@7223.52,3527.87 ; v1@7941.81,4202.99 ccw(c7925.59,4186.77) 7925.59,4209.71 ccw(c7925.59,4232.64) v1@7941.81,4216.43 ; v1@7944.64,4205.82 ccw(c7935.25,4196.43) 7935.25,4209.71 ccw(c7935.25,4222.99) v1@7944.64,4213.6
DB_MEM.BUS_A12: U7.D6 U8.AE26 U12.22 U13.22 U16.23 U17.23 U61.98 | length 7631.5
  Top Layer w4: U61.98@5645.91,2821.32 cw(c5639.08,2814.49) 5648.74,2814.49 cw(c5658.4,2814.49) U61.98@5651.57,2821.32 ; U8.AE26@5882.13,3737.24 5910,3737.24 5920,3737.24 5924.74,3737.24 ; U8.AE26@5887.32,3732.05 cw(c5899.85,3719.52) 5899.85,3737.24 cw(c5899.85,3754.97) U8.AE26@5887.32,3742.44 ; U8.AE26@5887.43,3731.94 cw(c5900.23,3719.14) 5900.23,3737.24 cw(c5900.23,3755.35) U8.AE26@5887.43,3742.55 ; 5923.52,3737.24 5931.32,3737.24 5938.19,3730.38 5938.19,3724.81 5953,3710 5953,3674.6 5944.02,3665.62 5944.02,3632.71 5929.19,3617.88 5929.19,3525.04 5941.2,3513.03 6061.51,3513.03 U13.22@6170.59,3513.03 6260.53,3513.03 6269.74,3503.82 6298.52,3475.04 6298.52,3391.71 v1(6281.86,3375.04) ; U13.22@6147.37,3507.37 ccw(c6133.72,3493.72) 6133.72,3513.03 ccw(c6133.72,3532.35) U13.22@6147.37,3518.69 ; U13.22@6193.81,3507.37 cw(c6207.46,3493.72) 6207.46,3513.03 cw(c6207.46,3532.35) U13.22@6193.81,3518.69 ; v1@6281.86,3380.54 ccw(c6281.86,3393.82) 6291.25,3384.43 ccw(c6300.64,3375.04) v1@6287.36,3375.04 ; v1@6281.86,3384.54 ccw(c6281.86,3407.48) 6298.07,3391.26 ccw(c6314.29,3375.04) v1@6291.36,3375.04 ; v1(6331.86,3143.04) 6381.86,3143.04 6398.52,3159.71 6398.52,3360 6389.19,3369.33 v1(6389.19,3408.37) ; v1@6335.75,3139.15 cw(c6345.14,3129.76) 6345.14,3143.04 cw(c6345.14,3156.32) v1@6335.75,3146.93 ; v1@6338.57,3136.32 cw(c6354.79,3120.11) 6354.79,3143.04 cw(c6354.79,3165.98) v1@6338.57,3149.76 ; v1(6348.52,2941.71) 6368.86,2941.71 ; v1@6352.74,2938.18 cw(c6360.3,2931.86) 6360.3,2941.71 cw(c6360.3,2951.55) v1@6352.74,2945.24 ; v1@6355.81,2935.61 cw(c6368.86,2924.7) 6368.86,2941.71 ; v1@6355.81,2947.8 ccw(c6368.86,2958.72) 6368.86,2941.71 ; v1@6382.47,3401.66 cw(c6366.26,3385.44) 6389.19,3385.44 cw(c6412.13,3385.44) v1@6395.91,3401.66 ; v1@6385.3,3404.49 cw(c6375.91,3395.1) 6389.19,3395.1 cw(c6402.47,3395.1) v1@6393.08,3404.49 ; U17.23@6619.41,4309.29 6651.61,4309.29 ; U17.23@6643.7,4304.97 cw(c6651.61,4299.9) 6651.61,4309.29 ; U17.23@6643.7,4313.61 ccw(c6651.61,4318.68) 6651.61,4309.29 ; v1(6665.19,4295.71) 6651.61,4309.29 ; v1(6788.52,3409.04) 6806.86,3427.37 6806.86,3504.7 6815.19,3513.03 ; v1@6788.52,3414.54 ccw(c6788.52,3427.82) 6797.91,3418.43 ccw(c6807.3,3409.04) v1@6794.02,3409.04 ; v1@6788.52,3418.54 ccw(c6788.52,3441.48) 6804.74,3425.26 ccw(c6820.96,3409.04) v1@6798.02,3409.04 ; U12.22@6820.85,3509.5 ccw(c6815.19,3506.72) 6815.19,3513.03 ; U12.22@6820.85,3516.56 cw(c6815.19,3519.34) 6815.19,3513.03 ; U12.22@6845.59,3513.03 6815.19,3513.03 ; v1(7186.19,4285.37) 7202.19,4285.37 ; v1@7194.53,4280.83 cw(c7202.19,4276.65) 7202.19,4285.37 ; v1@7194.53,4289.92 ccw(c7202.19,4294.1) 7202.19,4285.37 ; U16.23@7271.19,4303.64 ccw(c7257.54,4289.98) 7257.54,4309.29 ccw(c7257.54,4328.61) U16.23@7271.19,4314.95 ; U16.23@7294.41,4309.29 7226.11,4309.29 7202.19,4285.37 ; U61.98@5648.74,2836.46 5648.74,2786.68 5660.42,2775 5660.42,2716.12 5701,2675.55 5701,2516.63 5734.25,2483.37 5946.54,2483.37 6125.92,2662.75 6125.92,2677.44 6173.52,2725.04 6223.52,2725.04 6231.86,2733.37 6265.19,2733.37 6348.52,2816.71 6368.86,2816.71 6381.86,2829.71 6381.86,2928.71 6368.86,2941.71 ; U61.98@5648.74,2836.46 U61.98@5648.74,2837.34 U61.98@5648.74,2836.46
  Top Layer w8: U7.D6@7869.69,4419.94 cw(c7869.69,4405.46) 7879.93,4415.7 cw(c7890.17,4425.94) U7.D6@7875.69,4425.94 ; U7.D6@7869.69,4425.94 v2(7889.37,4406.26) ; v2@7880.37,4406.26 ccw(c7858.64,4406.26) 7874.01,4421.62 ccw(c7889.37,4436.99) v2@7889.37,4415.26
  MidLayer1 w4: v1(6331.86,3143.04) 6345.52,3129.37 6345.52,2944.71 v1(6348.52,2941.71) ; v1@6341.81,2948.43 ccw(c6332.83,2957.4) 6345.52,2957.4 ; 6345.52,2962.23 ccw(c6369.04,2962.23) v1@6352.41,2945.6 ; 6345.52,2971.89 ccw(c6378.7,2971.89) v1@6355.24,2948.43 ; v1(6734.86,3355.37) v1(6788.52,3409.04) 6865.19,3485.71 6865.19,3550.04 6890.19,3575.04 6915.08,3575.04 7056.74,3716.71 7066.19,3716.71 7081.86,3732.37 7081.86,4119.08 7186.19,4223.41 v1(7186.19,4285.37) ; v1@6734.86,3360.87 ccw(c6734.86,3374.15) 6744.25,3364.76 ccw(c6753.64,3355.37) v1@6740.36,3355.37 ; v1@6734.86,3364.87 ccw(c6734.86,3387.81) 6751.07,3371.59 ccw(c6767.29,3355.37) v1@6744.36,3355.37 ; v1@6779.02,3409.04 cw(c6756.09,3409.04) 6772.31,3392.82 cw(c6788.52,3376.61) v1@6788.52,3399.54 ; v1@6783.02,3409.04 cw(c6769.75,3409.04) 6779.14,3399.65 cw(c6788.52,3390.26) v1@6788.52,3403.54 ; v1@6788.52,3414.54 ccw(c6788.52,3427.82) 6797.91,3418.43 ccw(c6807.3,3409.04) v1@6794.02,3409.04 ; v1@6788.52,3418.54 ccw(c6788.52,3441.48) 6804.74,3425.26 ccw(c6820.96,3409.04) v1@6798.02,3409.04 ; v1@7179.47,4278.66 cw(c7163.26,4262.44) 7186.19,4262.44 cw(c7209.13,4262.44) v1@7192.91,4278.66 ; v1@7182.3,4281.49 cw(c7172.91,4272.1) 7186.19,4272.1 cw(c7199.47,4272.1) v1@7190.08,4281.49
  MidLayer2 w4: v1(6665.19,4295.71) 6670.86,4301.37 6782.52,4301.37 6791.86,4310.71 6973.52,4310.71 7000.86,4283.37 7138.19,4283.37 7154.86,4266.71 7167.52,4266.71 v1(7186.19,4285.37) ; v1@7176.69,4285.37 cw(c7153.76,4285.37) 7169.97,4269.16 cw(c7186.19,4252.94) v1@7186.19,4275.87 ; v1@7180.69,4285.37 cw(c7167.41,4285.37) 7176.8,4275.99 cw(c7186.19,4266.6) v1@7186.19,4279.87
  Bottom Layer w4: v1@6280.52,3376.37 6312.52,3408.37 v1(6389.19,3408.37) 6406.19,3425.37 6654.21,3425.37 6662.87,3416.71 6673.52,3416.71 v1(6734.86,3355.37) ; v1@6281.86,3384.54 ccw(c6281.86,3401.04) 6293.52,3389.37 ; v1@6287.36,3375.04 cw(c6307.07,3375.04) 6293.13,3388.98 ; v1@6291.36,3375.04 cw(c6320.73,3375.04) 6299.96,3395.81 ; v1@6382.47,3401.66 ccw(c6366.26,3385.44) 6366.26,3408.37 ccw(c6366.26,3431.31) v1@6382.47,3415.09 ; v1@6385.3,3404.49 ccw(c6375.91,3395.1) 6375.91,3408.37 ccw(c6375.91,3421.65) v1@6385.3,3412.26 ; v1@6389.19,3413.87 ccw(c6389.19,3427.15) 6398.58,3417.76 ccw(c6407.97,3408.37) v1@6394.69,3408.37 ; v1@6389.19,3417.87 ccw(c6389.19,3440.81) 6405.41,3424.59 ccw(c6421.63,3408.37) v1@6398.69,3408.37 ; v1@6725.36,3355.37 ccw(c6702.42,3355.37) 6718.64,3371.59 ccw(c6734.86,3387.81) v1@6734.86,3364.87 ; v1@6729.36,3355.37 ccw(c6716.08,3355.37) 6725.47,3364.76 ccw(c6734.86,3374.15) v1@6734.86,3360.87 ; v1@7179.47,4292.09 ccw(c7163.26,4308.31) 7186.19,4308.31 ccw(c7209.13,4308.31) v1@7192.91,4292.09 ; v1@7182.3,4289.26 ccw(c7172.91,4298.65) 7186.19,4298.65 ccw(c7199.47,4298.65) v1@7190.08,4289.26 ; v1(7186.19,4285.37) 7186.19,4308.37 7177.86,4316.71 7153.19,4316.71 7131.86,4295.37 7131.86,4258.71 7148.86,4241.71 7373.52,4241.71 7406.86,4275.04 7600.04,4275.04 7608.37,4283.37 7962.86,4283.37 7987.86,4308.37 7987.86,4336.04 7998.52,4346.71 8015.19,4346.71 8031.86,4363.37 8031.86,4370.37 8015.19,4387.04 7999.52,4387.04 7987.86,4398.71 7987.86,4416.71 7978.67,4425.89 7909,4425.89 v2(7889.37,4406.26)
DB_MEM.BUS_A13: U7.B7 U8.M26 U12.35 U13.35 U16.24 U17.24 U61.100 | length 8648.6
  Top Layer w4: v1(5600.86,2775.04) 5609.37,2783.55 U61.100@5609.37,2837.34 ; U61.100@5606.54,2821.32 cw(c5599.71,2814.49) 5609.37,2814.49 cw(c5619.03,2814.49) U61.100@5612.2,2821.32 ; U8.M26@5882.13,4249.06 5910,4249.06 5920,4249.06 5924.74,4249.06 5945,4249.05 5994.01,4200.04 6048.52,4200.04 6106.86,4258.37 6254.52,4258.37 v1(6281.52,4231.37) ; U8.M26@5887.32,4243.86 cw(c5899.85,4231.33) 5899.85,4249.06 cw(c5899.85,4266.78) U8.M26@5887.32,4254.25 ; U8.M26@5887.43,4243.75 cw(c5900.23,4230.95) 5900.23,4249.06 cw(c5900.23,4267.16) U8.M26@5887.43,4254.36 ; v1@6272.02,4231.37 ccw(c6249.09,4231.37) 6265.31,4247.59 ccw(c6281.52,4263.81) v1@6281.52,4240.87 ; v1@6276.02,4231.37 ccw(c6262.75,4231.37) 6272.14,4240.76 ccw(c6281.52,4250.15) v1@6281.52,4236.87 ; v1(6473.52,2465.04) 6500.19,2491.71 6556.86,2491.71 6573.52,2508.37 6573.52,2766.71 v1(6648.52,2841.71) ; v1@6473.52,2470.54 ccw(c6473.52,2483.82) 6482.91,2474.43 ccw(c6492.3,2465.04) v1@6479.02,2465.04 ; v1@6473.52,2474.54 ccw(c6473.52,2497.48) 6489.74,2481.26 ccw(c6505.96,2465.04) v1@6483.02,2465.04 ; v1@6566.81,4231.76 ccw(c6550.59,4247.98) 6573.52,4247.98 ccw(c6596.46,4247.98) v1@6580.24,4231.76 ; v1@6569.64,4228.93 ccw(c6560.25,4238.32) 6573.52,4238.32 ccw(c6586.8,4238.32) v1@6577.41,4228.93 ; v1(6573.52,4225.04) 6573.52,4265 6580,4271.48 6580,4335 6585.79,4340.79 ; U17.24@6595.47,4335.97 ccw(c6585.79,4328.66) 6585.79,4340.79 ; U17.24@6595.47,4345.61 cw(c6585.79,4352.91) 6585.79,4340.79 ; U13.35@6619.41,3576.02 6656.17,3576.02 ; U17.24@6619.41,4340.79 6585.79,4340.79 ; v1@6639.02,2841.71 cw(c6616.09,2841.71) 6632.31,2825.49 cw(c6648.52,2809.27) v1@6648.52,2832.21 ; U13.35@6642.65,3570.39 cw(c6656.17,3556.98) 6656.17,3576.02 ; U13.35@6642.65,3581.66 ccw(c6656.17,3595.07) 6656.17,3576.02 ; v1@6643.02,2841.71 cw(c6629.75,2841.71) 6639.14,2832.32 cw(c6648.52,2822.93) v1@6648.52,2836.21 ; v1@6680.69,3610.04 cw(c6657.76,3610.04) 6673.97,3593.82 cw(c6690.19,3577.61) v1@6690.19,3600.54 ; v1@6684.69,3610.04 cw(c6671.41,3610.04) 6680.8,3600.65 cw(c6690.19,3591.26) v1@6690.19,3604.54 ; v1(6690.19,3610.04) 6656.17,3576.02 ; v1(7125.52,3677.04) 7144.77,3696.28 7182.61,3696.28 7248.52,3630.37 7248.52,3584.02 7256.52,3576.02 U12.35@7294.41,3576.02 ; v1@7125.52,3682.54 ccw(c7125.52,3695.82) 7134.91,3686.43 ccw(c7144.3,3677.04) v1@7131.02,3677.04 ; v1@7125.52,3686.54 ccw(c7125.52,3709.48) 7141.74,3693.26 ccw(c7157.96,3677.04) v1@7135.02,3677.04 ; v1@7145.81,3892.09 ccw(c7129.59,3908.31) 7152.52,3908.31 ccw(c7175.46,3908.31) v1@7159.24,3892.09 ; v1@7148.64,3889.26 ccw(c7139.25,3898.65) 7152.52,3898.65 ccw(c7165.8,3898.65) v1@7156.41,3889.26 ; v1(7152.52,3885.37) 7152.52,3929.04 7181.86,3958.37 7181.86,4240 7191.86,4250 7370,4250 7385.19,4265.19 v1(7385.19,4291.71) 7385.19,4329.81 7374.21,4340.79 U16.24@7294.41,4340.79 ; U12.35@7271.19,3570.37 ccw(c7257.54,3556.71) 7257.54,3576.02 ccw(c7257.54,3595.34) U12.35@7271.19,3581.68 ; U16.24@7317.63,4335.13 cw(c7331.28,4321.47) 7331.28,4340.79 cw(c7331.28,4360.1) U16.24@7317.63,4346.44 ; v1@7378.47,4284.99 cw(c7362.26,4268.77) 7385.19,4268.77 cw(c7408.13,4268.77) v1@7391.91,4284.99 ; v1@7378.47,4298.43 ccw(c7362.26,4314.64) 7385.19,4314.64 ccw(c7408.13,4314.64) v1@7391.91,4298.43 ; v1@7381.3,4287.82 cw(c7371.91,4278.43) 7385.19,4278.43 cw(c7398.47,4278.43) v1@7389.08,4287.82 ; v1@7381.3,4295.6 ccw(c7371.91,4304.99) 7385.19,4304.99 ccw(c7398.47,4304.99) v1@7389.08,4295.6
  Top Layer w8: U7.B7@7948.43,4380.57 cw(c7948.43,4366.09) 7958.67,4376.33 cw(c7968.91,4386.57) U7.B7@7954.43,4386.57 ; U7.B7@7948.43,4386.57 v2(7968.11,4366.89) ; v2@7959.11,4366.89 ccw(c7937.38,4366.89) 7952.75,4382.25 ccw(c7968.11,4397.62) v2@7968.11,4375.89
  MidLayer1 w4: v1(6648.52,2841.71) 6691.19,2884.37 6715.19,2884.37 6723.52,2892.71 6723.52,2918.37 6715.19,2926.71 6715.19,3333.37 ; v1@6648.52,2847.21 ccw(c6648.52,2860.49) 6657.91,2851.1 ccw(c6667.3,2841.71) v1@6654.02,2841.71 ; v1@6648.52,2851.21 ccw(c6648.52,2874.14) 6664.74,2857.93 ccw(c6680.96,2841.71) v1@6658.02,2841.71 ; v1@6683.47,3603.32 cw(c6667.26,3587.11) 6690.19,3587.11 cw(c6713.13,3587.11) v1@6696.91,3603.32 ; v1@6686.3,3606.15 cw(c6676.91,3596.76) 6690.19,3596.76 cw(c6703.47,3596.76) v1@6694.08,3606.15 ; v1(6690.19,3610.04) 6690.19,3557 6697.19,3550 6697.19,3522.37 6731.86,3487.71 6731.86,3463.73 6707.86,3439.73 6707.86,3394.69 6715.19,3387.36 6715.19,3333.37 ; v1@7116.02,3677.04 cw(c7093.09,3677.04) 7109.31,3660.82 cw(c7125.52,3644.61) v1@7125.52,3667.54 ; v1@7120.02,3677.04 cw(c7106.75,3677.04) 7116.14,3667.65 cw(c7125.52,3658.26) v1@7125.52,3671.54 ; v1(7125.52,3677.04) 6965.19,3516.71 6965.19,3450.04 6940.19,3425.04 6873.52,3425.04 6781.86,3333.37 6715.19,3333.37
  MidLayer2 w4: v1(5600.86,2775.04) 5625.86,2800.04 5676.52,2800.04 5806.86,2669.71 5806.86,2521.52 5870,2458.37 6215.19,2458.37 6223.52,2466.71 6256.86,2466.71 v1(6298.52,2425.04) ; v1@5600.86,2780.54 ccw(c5600.86,2793.82) 5610.25,2784.43 ccw(c5619.64,2775.04) v1@5606.36,2775.04 ; v1@5600.86,2784.54 ccw(c5600.86,2807.48) 5617.07,2791.26 ccw(c5633.29,2775.04) v1@5610.36,2775.04 ; v1@6289.02,2425.04 ccw(c6266.09,2425.04) 6282.31,2441.26 ccw(c6298.52,2457.48) v1@6298.52,2434.54 ; v1@6293.02,2425.04 ccw(c6279.75,2425.04) 6289.14,2434.43 ccw(c6298.52,2443.82) v1@6298.52,2430.54 ; v1(6573.52,4225.04) 6596.54,4225.04 6605.54,4234.04 6886.86,4234.04 6895.52,4242.71 6982.86,4242.71 6998.52,4258.37 7058.19,4258.37 7073.52,4243.04 7073.52,4228.37 7085.19,4216.71 7198.52,4216.71 7281.86,4300.04 7376.86,4300.04 v1(7385.19,4291.71) ; v1@6577.41,4221.15 cw(c6586.8,4211.76) 6586.8,4225.04 cw(c6586.8,4238.32) v1@6577.41,4228.93 ; v1@6580.24,4218.32 cw(c6596.46,4202.11) 6596.46,4225.04 cw(c6596.46,4247.98) v1@6580.24,4231.76 ; 7342.14,4300.04 cw(c7342.14,4248.66) v1@7378.47,4284.99 ; 7351.79,4300.04 cw(c7351.79,4258.31) v1@7381.3,4287.82 ; 7361.45,4300.04 cw(c7361.45,4267.97) v1@7384.13,4290.65 ; 7371.11,4300.04 cw(c7371.11,4277.63) v1@7386.96,4293.48
  Bottom Layer w4: v1(6281.52,4231.37) 6300.19,4250.04 6548.52,4250.04 v1(6573.52,4225.04) ; v1@6281.52,4236.87 ccw(c6281.52,4250.15) 6290.91,4240.76 ccw(c6300.3,4231.37) v1@6287.02,4231.37 ; v1@6281.52,4240.87 ccw(c6281.52,4263.81) 6297.74,4247.59 ccw(c6313.96,4231.37) v1@6291.02,4231.37 ; v1@6298.52,2415.54 cw(c6298.52,2392.61) 6314.74,2408.82 cw(c6330.96,2425.04) v1@6308.02,2425.04 ; v1@6298.52,2419.54 cw(c6298.52,2406.26) 6307.91,2415.65 cw(c6317.3,2425.04) v1@6304.02,2425.04 ; v1(6298.52,2425.04) 6323.52,2400.04 6408.52,2400.04 v1(6473.52,2465.04) ; v1@6464.02,2465.04 cw(c6441.09,2465.04) 6457.31,2448.82 cw(c6473.52,2432.61) v1@6473.52,2455.54 ; v1@6468.02,2465.04 cw(c6454.75,2465.04) 6464.14,2455.65 cw(c6473.52,2446.26) v1@6473.52,2459.54 ; v1@6564.02,4225.04 ccw(c6541.09,4225.04) 6557.31,4241.26 ccw(c6573.52,4257.48) v1@6573.52,4234.54 ; v1@6568.02,4225.04 ccw(c6554.75,4225.04) 6564.14,4234.43 ccw(c6573.52,4243.82) v1@6573.52,4230.54 ; v1(7125.52,3677.04) 7165.19,3716.71 7165.19,3760 ; v1@7125.52,3682.54 ccw(c7125.52,3695.82) 7134.91,3686.43 ccw(c7144.3,3677.04) v1@7131.02,3677.04 ; v1@7125.52,3686.54 ccw(c7125.52,3709.48) 7141.74,3693.26 ccw(c7157.96,3677.04) v1@7135.02,3677.04 ; v1@7143.02,3885.37 cw(c7120.09,3885.37) 7136.31,3869.16 cw(c7152.52,3852.94) v1@7152.52,3875.87 ; v1@7147.02,3885.37 cw(c7133.75,3885.37) 7143.14,3875.99 cw(c7152.52,3866.6) v1@7152.52,3879.87 ; v1(7152.52,3885.37) 7123.19,3856.04 7123.19,3808.35 7165,3766.55 7165,3760 ; v1(7385.19,4291.71) 7448.52,4291.71 7473.52,4316.71 7589.52,4316.71 7614.52,4291.71 7881.86,4291.71 7909.52,4319.37 7909.52,4336.7 7920,4347.17 7948.39,4347.17 v2(7968.11,4366.89) ; v1@7389.08,4287.82 cw(c7398.47,4278.43) 7398.47,4291.71 cw(c7398.47,4304.99) v1@7389.08,4295.6 ; v1@7391.91,4284.99 cw(c7408.13,4268.77) 7408.13,4291.71 cw(c7408.13,4314.64) v1@7391.91,4298.43 ; v2@7957.11,4366.89 cw(c7930.55,4366.89) 7949.33,4348.11 cw(c7968.11,4329.33) v2@7968.11,4355.89 ; v2@7961.11,4366.89 cw(c7944.21,4366.89) 7956.16,4354.94 cw(c7968.11,4342.99) v2@7968.11,4359.89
